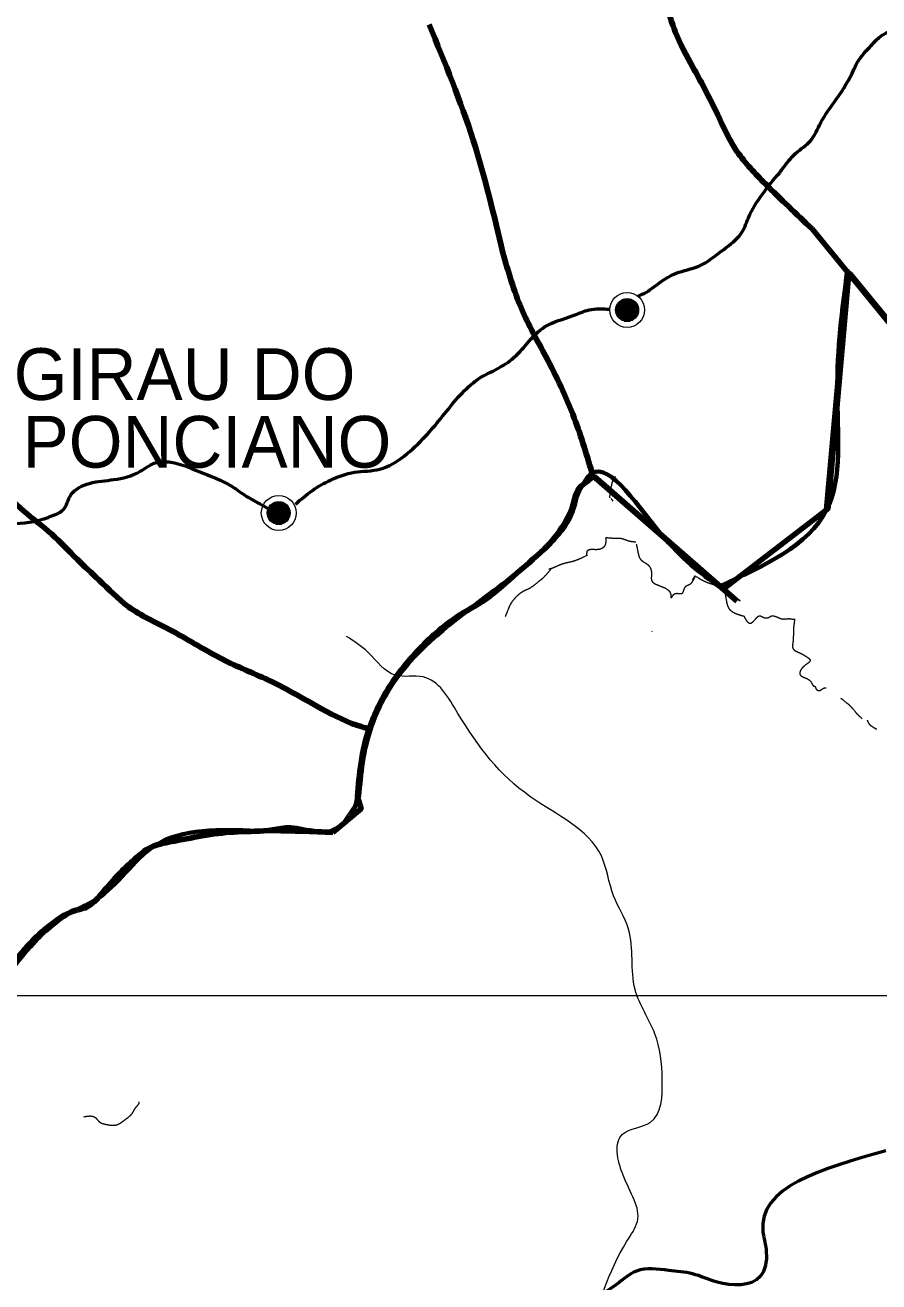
# Model space of a CAD drawing. Extents: x 512883 to 1063249, y 8784064 to 9081064.
# Drawn here: x 730709 to 755485, y 8884279 to 8920736 of the extents above; entities that cross this region are included whole.
import ezdxf

# ---------------------------------------------------------------- set-up
doc = ezdxf.new("R2010")
doc.units = 0
doc.header["$LTSCALE"] = 600
doc.linetypes.add('DOT_DASHED', pattern=[7.7, 5, -1.2, 0.3, -1.2])
for name, color, linetype, lineweight in [('1', 7, 'Continuous', 25), ('10', 7, 'Continuous', 53), ('13', 7, 'Continuous', 90), ('4', 7, 'Continuous', 13), ('5', 7, 'Continuous', 13)]:
    doc.layers.add(name, color=color, linetype=linetype, lineweight=lineweight)

msp = doc.modelspace()

# ---------------------------------------------------------------- linework, layer by layer
at = {"layer": '1', "lineweight": 13}
msp.add_line((581090.6, 8892594.3), (934660.9, 8892579.8), dxfattribs=at)
at = {"layer": '10'}
for points in [[(752606.4, 8916455.3), (752680.1, 8916557), (753079.8, 8917025.8), (753499.6, 8917382), (753799.4, 8917907), (754259.1, 8918600.7), (754759.7, 8919445.8), (754818.7, 8919575.7), (755218.5, 8920100.6), (755498.3, 8920381.9), (756257.1, 8920719.4)], [(748500.3, 8912876.7), (748724.9, 8912984.1), (748969.2, 8913150.2), (749602, 8913538.4), (750261.6, 8913744.7), (750981.2, 8914232.1), (751480.8, 8914682.1), (751700.7, 8915150.8), (752606.4, 8916455.3)], [(743708, 8910353.7), (743725.7, 8910369.8), (744365.3, 8910744.8), (744905, 8911101), (745784.4, 8911982.2), (746615, 8912309.9), (747074.1, 8912476), (747670, 8912495.6)], [(738555.6, 8906838.9), (739048.7, 8907238.7), (739568.3, 8907538.7), (740267.9, 8907763.6), (741007.4, 8907857.4), (741707, 8908232.4), (742326.6, 8908813.6), (742766.3, 8909319.8), (743725.7, 8910369.8), (743857.3, 8910469.4)], [(728825.3, 8905506.4), (729035.2, 8905677.3), (729607.2, 8906173.3), (730163.8, 8906266.2), (731210.7, 8906400.6), (731430.3, 8906478), (731813.3, 8906679.5), (732038, 8907108.3), (732579.3, 8907444.1), (733284.1, 8907552.6), (734034.8, 8907785), (734519.9, 8908048.5), (734933.6, 8908058.8), (735750.6, 8907790.2), (736715.8, 8907351.1), (737134.6, 8907067), (737512.5, 8906855.2), (737772.9, 8906705.3)], [(755690.2, 8888084), (752119.9, 8885734.8), (752219, 8885133.7), (752040.6, 8884432.4), (750792.3, 8884272.1), (750079, 8884512.5), (749385.4, 8884612.7), (748454.1, 8884592.7), (747879.5, 8884211.9), (746651, 8883370.3), (746016.9, 8882528.7), (745382.8, 8881446.7), (744867.7, 8880645.1)]]:
    msp.add_spline(points, degree=3, dxfattribs=at)
at = {"layer": '13'}
for p, q in [((763206.5, 8903037.7), (753545, 8914822.5)), ((747183, 8907663.5), (751360.9, 8904022.7))]:
    msp.add_line(p, q, dxfattribs=at)
at = {"layer": '13', "lineweight": 25}
for p, q in [((739733.3, 8897332.5), (740443.6, 8898367.2)), ((732569.4, 8895155.5), (732554, 8895148.6))]:
    msp.add_line(p, q, dxfattribs=at)
msp.add_lwpolyline([(747274.5, 8907680.2), (751452.5, 8904039.4), (751053.9, 8904386.7), (754060.3, 8906689.4), (754675.2, 8913572.2), (754687.7, 8913557), (763298.1, 8903054.4), (763439.1, 8903088.5)], dxfattribs=at)
at = {"layer": '13'}
for points in [[(750962.4, 8904370), (753968.8, 8906672.7), (754583.7, 8913555.5)], [(740352, 8898350.5), (740456.5, 8898005.6), (739641.8, 8897315.8)]]:
    msp.add_lwpolyline(points, dxfattribs=at)
for points in [[(731978.6, 8923288.5), (731414.5, 8922814.4), (730600.5, 8922061.6), (730145.5, 8921404.3), (729937.2, 8920644.5), (729637.8, 8919665.5), (729505.7, 8918554.4), (729120, 8917699), (728299.2, 8917099.6), (727420.7, 8916887.6), (726854.1, 8916471), (726595, 8915945.4), (726494.7, 8915479.3), (726726.5, 8914806.3), (726750.4, 8914269.8), (726694, 8913722.8), (726676.5, 8913209.7), (726820.4, 8912698.7), (727143.6, 8911787.2), (727604.4, 8910956.4), (728002.6, 8910170.4), (728573.4, 8909137.3), (729038.5, 8908210.8), (729883.7, 8907358.3), (730662.1, 8906646.5), (731479.3, 8905968.6), (732218, 8905241.9), (732850.2, 8904640.9), (733712.2, 8903862.9), (734891.9, 8903203.9), (736361.3, 8902380.6), (737671.2, 8901784.3)], [(753545, 8914822.5), (752195.2, 8916128.9), (751366, 8917075), (750725.9, 8918306.2), (750086.7, 8919518.2), (749576.8, 8920544.8), (749319.6, 8921334.9)], [(744573.3, 8914135.4), (743711.8, 8917396.6), (742432.8, 8920753.1)], [(747183, 8907663.5), (746645.8, 8909337.4), (745819.5, 8911122.2), (745111.8, 8912513.1), (744573.3, 8914135.4)], [(740352, 8898350.5), (740456.5, 8899327.8), (740707.2, 8900362.6), (741292.1, 8901550.7), (742106.8, 8902585.5), (743234.8, 8903562.8), (744070.4, 8904080.1), (744989.6, 8904846.6), (745887.8, 8905651.5), (746598.1, 8906762.9), (746786.1, 8907299.4), (747099.4, 8907567.7), (747183, 8907663.5)], [(737671.2, 8901784.3), (737824, 8901710.6), (739312.9, 8900904.2), (740486.6, 8900379.3), (740694.6, 8900324.9)], [(732462.4, 8895131.9), (732560.2, 8895188.7), (732957.1, 8895572), (733437.5, 8896108.5), (733813.6, 8896472.6), (734377.6, 8896894.2), (735046.1, 8897066.7), (735965.2, 8897239.1), (736884.3, 8897334.9), (737887.1, 8897392.4), (738409.3, 8897449.9), (738764.4, 8897392.4), (739641.8, 8897315.8)], [(729681.8, 8891142.3), (729656.5, 8891567), (729949, 8892601.8), (730450.3, 8893598.2), (731369.5, 8894575.5), (732017, 8894997.1), (732477.9, 8895138.8)]]:
    msp.add_spline(points, degree=3, dxfattribs=at)
at = {"layer": '13', "lineweight": 25}
for points in [[(740443.6, 8898367.2), (740548, 8899344.5), (740798.7, 8900379.3), (741383.6, 8901567.4), (742198.3, 8902602.2), (743326.4, 8903579.5), (744162, 8904096.8), (745081.1, 8904863.3), (745979.3, 8905668.2), (746689.6, 8906779.6), (746877.6, 8907316.2), (747191, 8907584.4), (747274.5, 8907680.2)], [(732554, 8895148.6), (732651.7, 8895205.4), (733048.6, 8895588.7), (733529.1, 8896125.2), (733905.1, 8896489.3), (734469.1, 8896910.9), (735137.6, 8897083.4), (736056.7, 8897255.8), (736975.9, 8897351.6), (737978.6, 8897409.1), (738500.8, 8897466.6), (738856, 8897409.1), (739733.3, 8897332.5)], [(729773.3, 8891159), (729748, 8891583.7), (730040.5, 8892618.5), (730541.8, 8893614.9), (731461, 8894592.2), (732108.6, 8895013.8), (732569.4, 8895155.5)]]:
    msp.add_spline(points, degree=3, dxfattribs=at)
at = {"layer": '4', "linetype": 'DOT_DASHED'}
for p, q in [((747709.7, 8907001.7), (747764.6, 8906925.9)), ((748897.2, 8903157.8), (748885.7, 8903137.7))]:
    msp.add_line(p, q, dxfattribs=at)
at = {"layer": '4', "lineweight": 70}
for points in [[(750863.4, 8904456.2), (753968.8, 8906672.7), (754276.2, 8910114.1), (754568, 8913622)], [(754568, 8913622), (758375.8, 8908930.1), (763410.8, 8903088)], [(739491.5, 8897319.2), (740049.1, 8897660.7), (740437.9, 8899153.6), (741034.8, 8901113.8), (743561.4, 8903764.3), (745471.9, 8905265.6), (746442.1, 8906464.9), (747159.6, 8907736.3), (749272, 8905843.1), (750962.4, 8904370)], [(729699, 8891025.9), (729748.4, 8892070.1), (730861.6, 8894002.8), (732096, 8895026.1), (732763.6, 8895371), (734460.9, 8896926.1), (737423.4, 8897366.9), (739641.8, 8897315.8)]]:
    msp.add_spline(points, degree=3, dxfattribs=at)
at = {"layer": '4', "linetype": 'DOT_DASHED'}
for points in [[(747676, 8907019.3), (747744, 8907444.4), (747795.2, 8907577.7), (747846.4, 8907644.4)], [(747015.8, 8905355.4), (747027.3, 8905485.9), (747339.6, 8905532), (747539.2, 8905639.7), (747564.8, 8905865.3)], [(748435.5, 8905738.9), (748225.3, 8905767.9), (748005.1, 8905839.7), (747846.4, 8905844.8), (747564.8, 8905865.3)], [(748444.5, 8905677), (748481.2, 8905506.4), (748568.3, 8905239.8), (748803.8, 8905060.4), (748885.7, 8904834.8), (748890.8, 8904629.7), (749208.2, 8904440), (749438.6, 8904245.2), (749446.7, 8904119.4)], [(747015.8, 8905355.4), (746587, 8905173.2), (746361.8, 8905121.9), (746121.2, 8905029.6), (745998.3, 8904978.3), (745911.3, 8904952.7)], [(744957.9, 8904150.7), (745148.7, 8904306.9), (745351.3, 8904405.7), (745554.1, 8904551.4), (745706.1, 8904671), (745853, 8904821.8), (745984.3, 8904974.2)], [(749463.9, 8904110.9), (749489.8, 8904163.1), (749571.7, 8904245.2), (749781.6, 8904260.6), (749843, 8904393.8), (749894.2, 8904465.6), (750032.4, 8904542.5), (750152.4, 8904760.1), (750068.3, 8904634.8)], [(750957.3, 8904440.1), (750411.3, 8904604.1), (750170.4, 8904745.6)], [(750957.3, 8904440.2), (751005.1, 8904301.6), (751071.7, 8903978.6), (751138.2, 8903804.2), (751215, 8903732.5), (751572.8, 8903592.5)], [(744972.7, 8904162.2), (744824.3, 8903989.6), (744702.7, 8903729.5), (744641.9, 8903578.7)], [(751572.9, 8903592.5), (751645.1, 8903455.6), (751727, 8903388.9), (751962.5, 8903568.4), (752008.5, 8903599.2), (752136.5, 8903558.1), (752295.2, 8903558.1), (752346.4, 8903588.9), (752679.2, 8903512), (752945.4, 8903512), (752991.5, 8903501.8), (753033.5, 8903506.6)], [(753040.4, 8903508.7), (753006.8, 8903189), (752991.5, 8902840.4), (752996.6, 8902645.5), (753175.8, 8902532.7), (753334.5, 8902445.6), (753488.1, 8902317.4), (753273, 8902102.1), (753196.2, 8901902.1), (753518.8, 8901681.7), (753616, 8901558.6), (753621.2, 8901558.6), (753651.9, 8901502.2), (753754.3, 8901430.4), (753897.6, 8901507.3), (753938.6, 8901512.5), (753953.9, 8901512.5), (753984.6, 8901492), (753979.5, 8901343.3), (753987.3, 8901334.9)], [(754997.1, 8900616.1), (754855, 8900753.7), (754696.2, 8900943.4), (754568.3, 8901061.3), (754384, 8901204.8)], [(755421.2, 8900308.3), (755198, 8900476.8), (755157, 8900569.1)], [(732416, 8889070.2), (732736.8, 8889052.8), (732865.2, 8888920.9), (733070.6, 8888844.8), (733342.8, 8888829.6), (733620, 8888991.9), (733825.4, 8889179.6), (733923, 8889341.9), (734020.5, 8889489.1), (734020.5, 8889504.3)]]:
    msp.add_spline(points, degree=3, dxfattribs=at)
at = {"layer": '4'}
msp.add_spline([(744501.9, 8869598.5), (744470, 8870556.5), (743738.4, 8872229.9), (744063.6, 8873152.6), (743349.9, 8874434.9), (743618.1, 8875934.2), (744918.6, 8879583.7), (745542.8, 8880277.2), (747016.9, 8882711.3), (748172.5, 8885457), (748475.8, 8886030.2), (748062.7, 8887371.4), (748049, 8888564.8), (748851.5, 8888906.8), (749198.3, 8890137.9), (748985.3, 8891477.2), (748411.7, 8892758.2), (748220.9, 8894508.7), (747785.8, 8895479.8), (747431.7, 8896635.3), (745359.3, 8898362.7), (743270.6, 8900769.2), (742255.5, 8901828.1), (741455.1, 8901876.9), (740658, 8902542.9), (740040, 8903001.4)], degree=3, dxfattribs=at)
at = {"layer": '5'}
for p, q in [((747929.3, 8912692), (748429.7, 8912692)), ((747958.4, 8912722), (748400, 8912722)), ((747998, 8912752), (748360.4, 8912752)), ((748055.3, 8912782), (748303.1, 8912782)), ((747846.8, 8912482), (748511.6, 8912482)), ((747847.4, 8912452), (748511.3, 8912452)), ((747848.9, 8912512), (748509.5, 8912512)), ((747850.4, 8912422), (748508, 8912422)), ((747853.7, 8912542), (748504.7, 8912542)), ((747856.4, 8912392), (748502, 8912392)), ((747861.8, 8912572), (748496.6, 8912572)), ((747865.4, 8912362), (748493, 8912362)), ((747872.6, 8912602), (748485.8, 8912602.3)), ((747878, 8912332), (748480.7, 8912332.3)), ((747887, 8912632), (748471.7, 8912632)), ((747905.3, 8912662), (748453.4, 8912662)), ((747893.9, 8912302), (748464.5, 8912302)), ((747914.6, 8912272), (748444.1, 8912272.3)), ((747939.8, 8912241.7), (748418.9, 8912242)), ((747973.1, 8912212), (748385.3, 8912212)), ((748018.1, 8912182), (748340.3, 8912182)), ((748091.9, 8912152), (748266.2, 8912152)), ((737887.9, 8906863.7), (738250.3, 8906863.7)), ((737945.2, 8906893.7), (738193, 8906893.7)), ((737736.7, 8906593.7), (738401.5, 8906593.7)), ((737737.3, 8906563.7), (738401.2, 8906563.7)), ((737738.8, 8906623.7), (738399.4, 8906623.7)), ((737740.3, 8906533.7), (738397.9, 8906533.7)), ((737743.6, 8906653.7), (738394.6, 8906653.7)), ((737746.3, 8906503.7), (738391.9, 8906503.7)), ((737751.7, 8906683.7), (738386.5, 8906683.7)), ((737755.3, 8906473.7), (738382.9, 8906473.7)), ((737762.5, 8906713.7), (738375.7, 8906714)), ((737776.9, 8906743.7), (738361.6, 8906743.7)), ((737795.2, 8906773.7), (738343.3, 8906773.7)), ((737819.2, 8906803.7), (738319.6, 8906803.7)), ((737848.3, 8906833.7), (738289.9, 8906833.7)), ((737767.9, 8906443.7), (738370.6, 8906444)), ((737783.8, 8906413.7), (738354.4, 8906413.7)), ((737804.5, 8906383.7), (738334, 8906384)), ((737829.7, 8906353.4), (738308.8, 8906353.7)), ((737863, 8906323.7), (738275.2, 8906323.7)), ((737908, 8906293.7), (738230.2, 8906293.7)), ((737981.8, 8906263.7), (738156.1, 8906263.7))]:
    msp.add_line(p, q, dxfattribs=at)
for centre, radius in [((748179.3, 8912473), 506.1), ((748179.3, 8912473), 332.9), ((738069.2, 8906584.7), 506.1), ((738069.2, 8906584.7), 332.9)]:
    msp.add_circle(centre, radius, dxfattribs=at)

# ---------------------------------------------------------------- texts
for s, p in [('GIRAU DO', (730376.6, 8909863.1)), ('PONCIANO', (730636.6, 8907899.8))]:
    msp.add_text(s, height=1500, dxfattribs=at).set_placement(p)

doc.saveas('drawing.dxf')
